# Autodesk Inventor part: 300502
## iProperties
Shininess: 64.0
Length Units: 11269
Angle Units: 11279
Time Units: 11290
Mass Units: 11283
Length Display Precision: 3
Angle Display Precision: 2
Compacted: True
Part Number: 300502
Document SubType Name: Sheet Metal
Created: 2002-12
Material: Byt material!
Description: Benämning på modell
Designer: NG
Density: 0.0
Volumn: 0.0
Area: 0.0
PropertySet Name: Model Information
Control State: 0
Master: False
Checked Out: False
Last Check In By: NG
Last Check In Date: 2002-12-11
Checked Out By: NG
Checked Out Date: 2002-12-11
r1: 0,600 mm
d54: 0,600 mm
f1: 2,500 mm
Vinkel: 15,00 deg
t1: 0,400 mm
d57: 90,00 deg
Author: NG
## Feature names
1. Revolution1
2. Chamfer1
3. Chamfer2
4. Chamfer3
5. Fillet1
6. Chamfer4
7. Hole2
8. Hole1
9. Chamfer5
10. Hole3
11. Chamfer6
12. Revolution2
